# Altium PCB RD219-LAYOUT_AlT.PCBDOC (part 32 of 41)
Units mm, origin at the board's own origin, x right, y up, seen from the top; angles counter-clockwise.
Board outline 209.75 x 159.97 mm, 2 copper layers (TOP, BOTTOM), stack 0 mm thick; 398 components, 199 nets, 1469 pads, 0 vias.
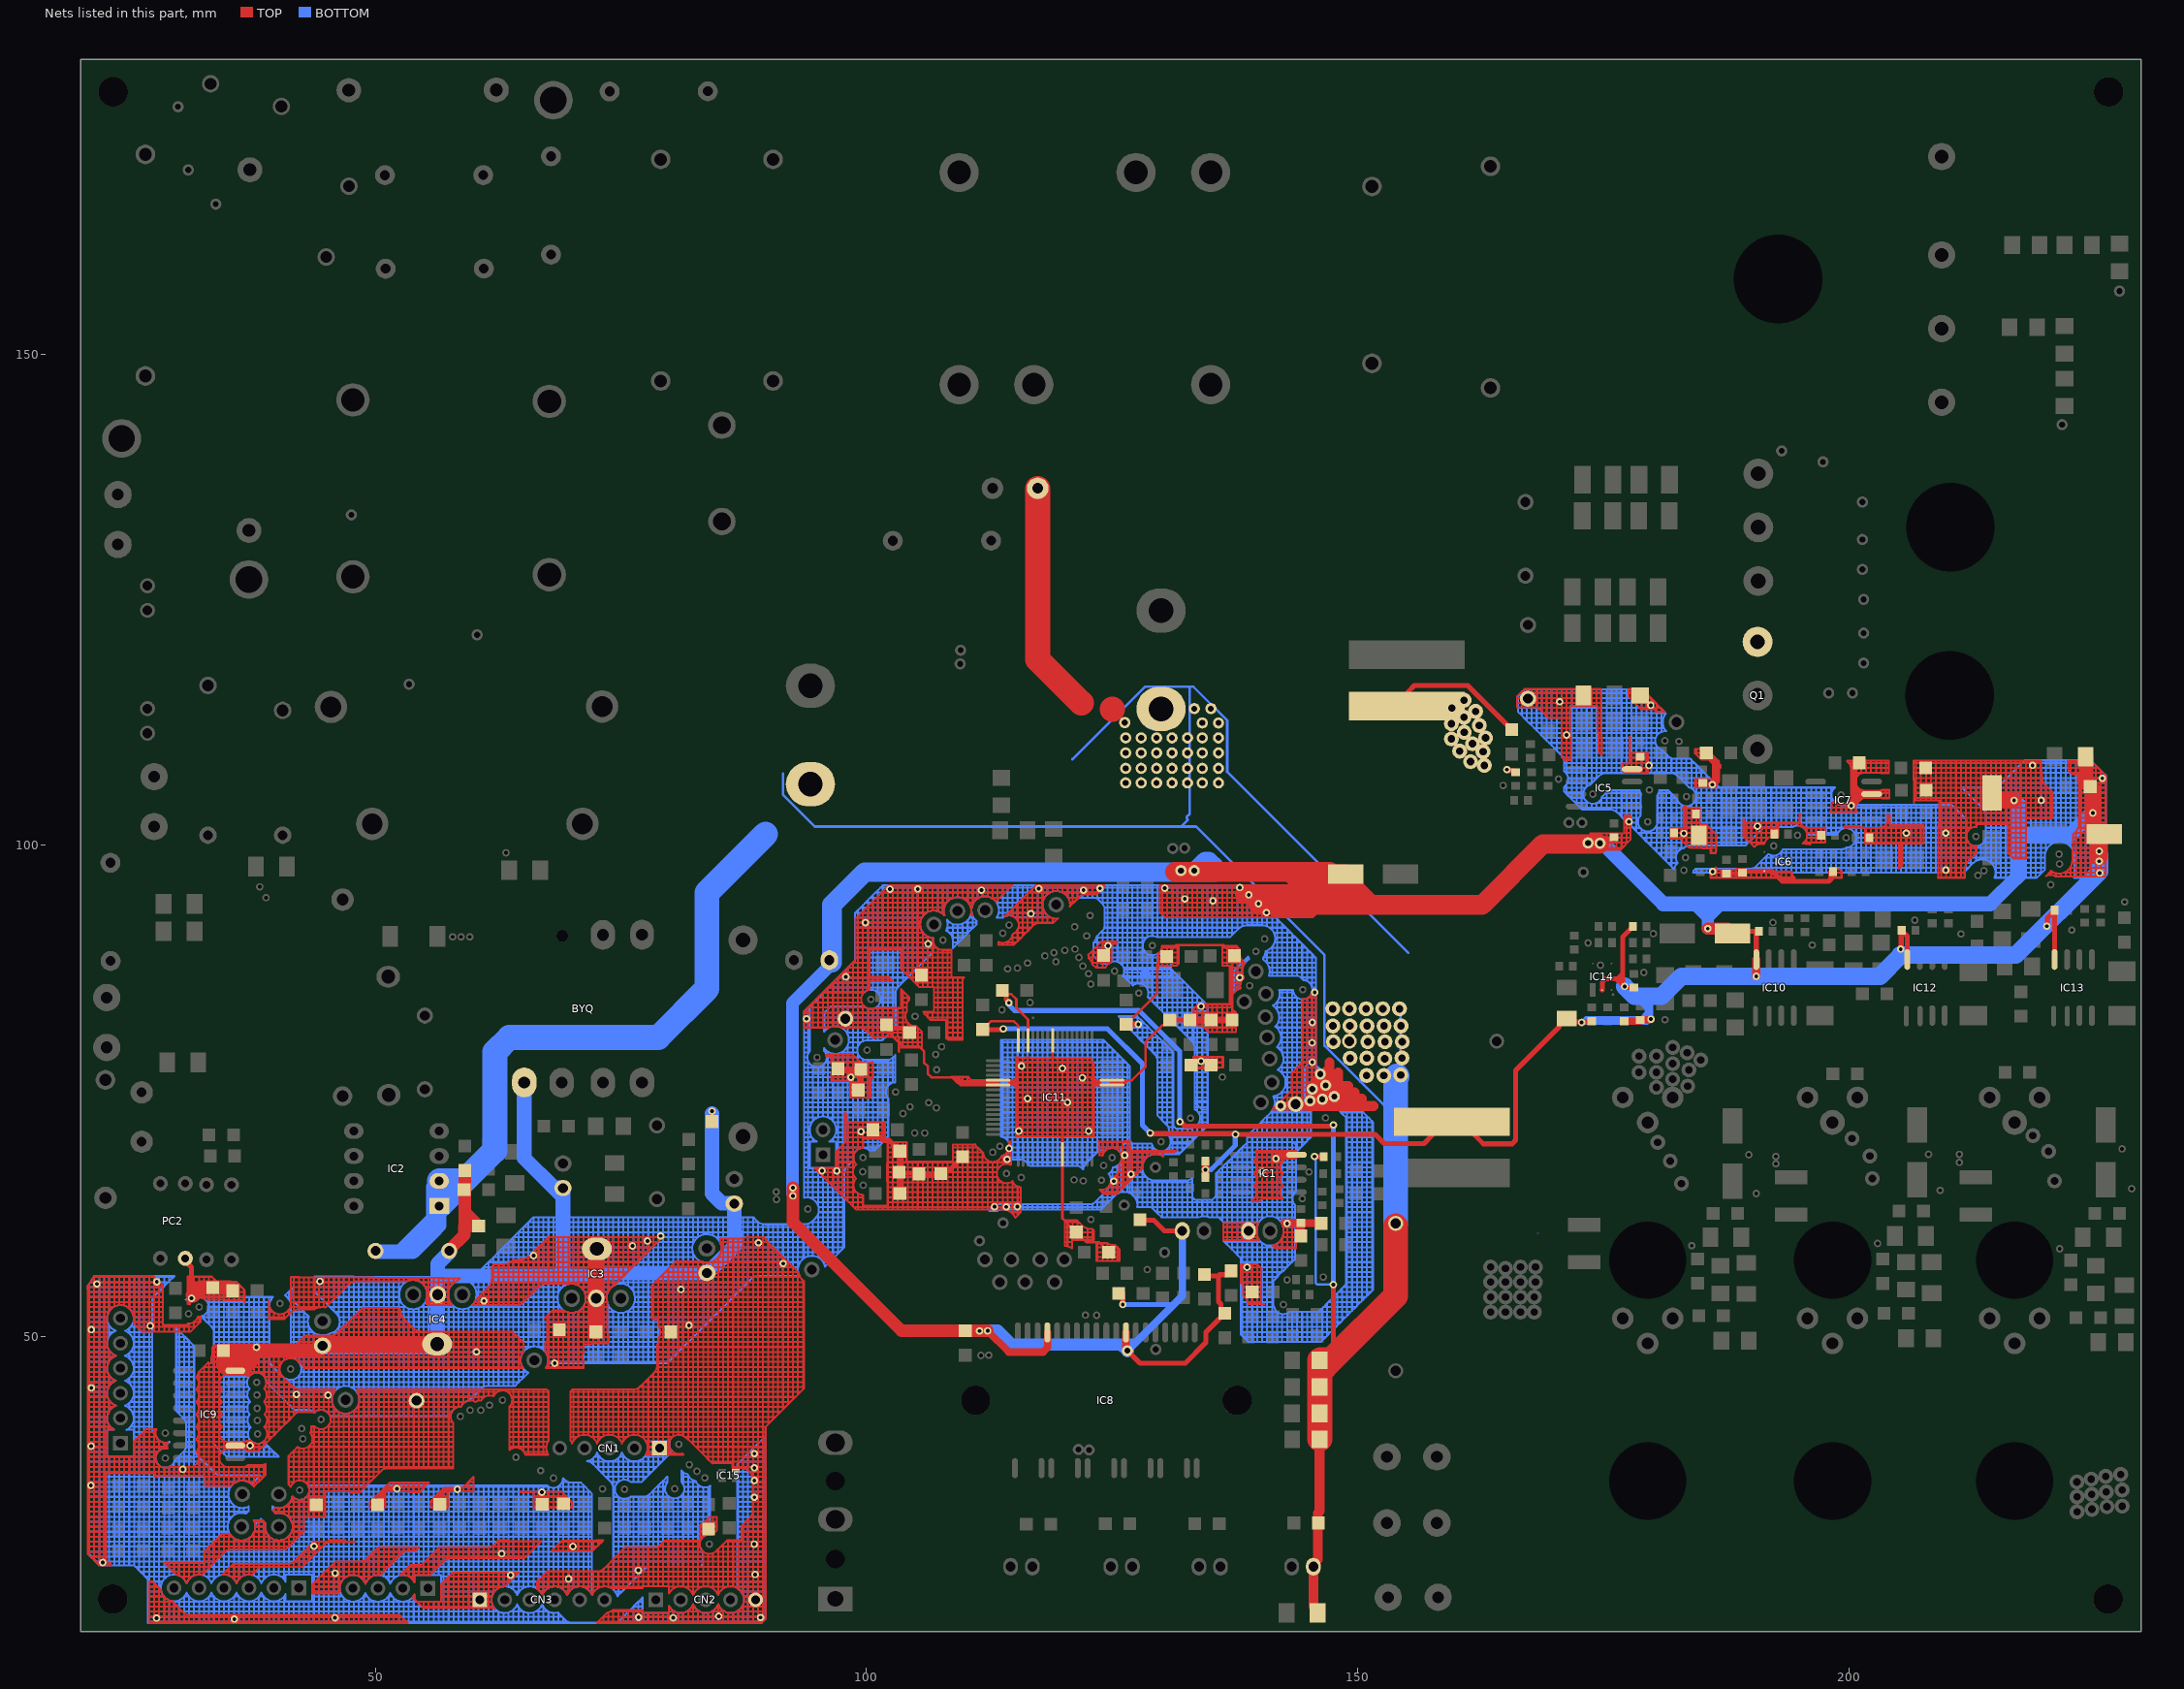
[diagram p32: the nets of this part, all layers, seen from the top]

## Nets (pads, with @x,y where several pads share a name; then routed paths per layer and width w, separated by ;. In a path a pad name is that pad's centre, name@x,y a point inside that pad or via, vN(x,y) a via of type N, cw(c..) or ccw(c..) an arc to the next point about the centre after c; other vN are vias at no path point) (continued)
GND: (continued)
  BOTTOM w0.203: 124.205,91.63 ccw(c123.505,91.831) 124.234,91.831 ; 124.205,91.63 ccw(c123.505,91.831) 124.234,91.831 ; 124.222,93.66 cw(c123.505,93.533) 124.234,93.533 ; 124.222,93.66 cw(c123.505,93.533) 124.234,93.533 ; 124.222,93.66 124.521,93.66 ; 124.234,91.831 124.234,92.136 ; 124.234,92.136 124.521,92.136 ; 124.234,92.136 124.234,92.644 ; 124.234,92.644 124.234,93.152 ; 124.234,92.644 124.521,92.644 ; 124.234,93.152 124.521,93.152 ; 124.234,93.152 124.234,93.533 ; 124.281,64.704 124.521,64.704 ; 124.281,64.704 124.421,64.843 ; 124.394,79.944 124.521,79.817 ; 124.421,64.843 ccw(c123.906,65.359) 124.521,64.968 ; 124.421,64.843 ccw(c123.906,65.359) 124.521,64.968 ; 124.521,63.599 124.521,63.688 ; 124.521,63.599 124.61,63.688 ; 124.521,63.688 124.61,63.688 ; 124.521,63.688 124.521,64.196 ; 124.521,64.196 125.029,64.196 ; 124.521,64.196 124.521,64.704 ; 124.521,64.704 125.029,64.704 ; 124.521,64.704 124.521,64.968 ; 124.521,64.968 ccw(c123.906,65.359) 124.619,65.212 ; 124.521,64.968 ccw(c123.906,65.359) 124.619,65.212 ; 124.521,69.09 124.521,69.276 ; 124.521,69.276 124.521,69.784 ; 124.521,69.276 125.029,69.276 ; 124.521,69.784 124.521,70.292 ; 124.521,69.784 125.029,69.784 ; 124.521,70.292 124.521,70.8 ; 124.521,70.292 125.029,70.292 ; 124.521,70.8 124.521,71.308 ; 124.521,70.8 125.029,70.8 ; 124.521,71.308 124.521,71.816 ; 124.521,71.308 125.029,71.308 ; 124.521,71.816 124.521,72.324 ; 124.521,71.816 125.029,71.816 ; 124.521,72.324 124.521,72.832 ; 124.521,72.324 125.029,72.324 ; 124.521,72.832 124.521,73.34 ; 124.521,72.832 125.029,72.832 ; 124.521,73.34 124.521,73.848 ; 124.521,73.34 125.029,73.34 ; 124.521,73.848 124.521,74.356 ; 124.521,73.848 125.029,73.848 ; 124.521,74.356 124.521,74.864 ; 124.521,74.356 125.029,74.356 ; 124.521,74.864 124.521,75.372 ; 124.521,74.864 125.029,74.864 ; 124.521,75.372 124.521,75.88 ; 124.521,75.372 125.029,75.372 ; 124.521,75.88 124.521,76.388 ; 124.521,75.88 125.029,75.88 ; 124.521,76.388 124.521,76.896 ; 124.521,76.388 125.029,76.388 ; 124.521,76.896 124.521,77.404 ; 124.521,76.896 125.029,76.896 ; 124.521,77.404 124.521,77.912 ; 124.521,77.404 125.029,77.404 ; 124.521,77.912 124.521,78.42 ; 124.521,77.912 125.029,77.912 ; 124.521,78.42 124.521,78.928 ; 124.521,78.42 125.029,78.42 ; 124.521,78.928 124.521,79.436 ; 124.521,78.928 125.029,78.928 ; 124.521,79.436 124.521,79.817 ; 124.521,79.436 124.902,79.436 ; 124.521,79.817 124.902,79.436 ; 124.521,87.934 124.521,88.072 ; 124.521,88.072 124.521,88.58 ; 124.521,88.072 124.786,88.072 ; 124.521,88.58 124.521,89.088 ; 124.521,88.58 125.029,88.58 ; 124.521,89.088 pad.@124.521,89.596 ; 124.521,89.088 125.029,89.088 ; pad.@124.521,89.596 pad.@124.521,90.104 ; pad.@124.521,89.596 125.029,89.596 ; pad.@124.521,90.104 124.521,90.612 ; pad.@124.521,90.104 125.029,90.104 ; 124.521,90.612 124.521,91.12 ; 124.521,90.612 125.029,90.612 ; 124.521,91.12 124.521,91.628 ; 124.521,91.12 125.029,91.12 ; 124.521,91.628 124.521,92.136 ; 124.521,91.628 125.029,91.628 ; 124.521,92.136 124.521,92.644 ; 124.521,92.136 125.029,92.136 ; 124.521,92.644 124.521,93.152 ; 124.521,92.644 125.029,92.644 ; 124.521,93.152 124.521,93.66 ; 124.521,93.152 125.029,93.152 ; 124.521,93.66 125.029,93.66 ; 124.521,93.66 124.521,94.168 ; 124.521,94.168 125.029,94.168 ; 124.521,94.168 124.521,94.676 ; 124.521,94.676 125.029,94.676 ; 124.521,94.676 124.521,95.184 ; 124.521,95.184 125.029,95.184 ; 124.521,95.184 124.521,95.692 ; 124.521,95.692 125.029,95.692 ; 124.521,95.692 124.521,95.946 ; 124.521,95.946 125.029,95.946 ; 124.61,63.688 125.029,64.107 ; 124.619,65.212 ccw(c123.906,65.359) 124.625,65.245 cw(c123.906,65.359) 124.619,65.212 ; 124.619,65.212 125.029,65.212 ; 124.786,88.072 cw(c125.249,87.205) 125.028,88.163 cw(c125.249,87.205) 125.029,88.163 ; 124.833,66.736 ccw(c124.133,67.425) 125.029,67.023 ; 124.833,66.736 125.029,66.736 ; 124.845,66.228 cw(c123.911,65.923) 124.894,65.923 cw(c123.911,65.923) pad.@124.872,65.72 ; 124.845,66.228 125.029,66.228 ; pad.@124.872,65.72 pad.@125.029,65.72 ; 124.902,79.436 125.029,79.309 ; 125.029,64.107 125.029,64.196 ; 125.029,64.107 125.118,64.196 ; 125.029,64.196 125.029,64.704 ; 125.029,64.196 125.118,64.196 ; 125.029,64.704 125.029,65.212 ; 125.029,64.704 125.537,64.704 ; 125.029,65.212 pad.@125.029,65.72 ; 125.029,65.212 125.537,65.212 ; pad.@125.029,65.72 125.029,66.228 ; pad.@125.029,65.72 125.537,65.72 ; 125.029,66.228 125.029,66.736 ; 125.029,66.228 125.537,66.228 ; 125.029,66.736 125.537,66.736 ; 125.029,66.736 125.029,67.023 ; 125.029,67.023 ccw(c124.133,67.425) 125.03,67.025 ccw(c124.133,67.425) 125.098,67.244 ; 125.029,69.276 125.029,69.784 ; 125.029,69.276 125.537,69.276 ; 125.029,69.276 125.029,69.21 cw(c124.994,68.228) 125.537,69.047 ; 125.029,69.784 125.029,70.292 ; 125.029,69.784 125.537,69.784 ; 125.029,70.292 125.029,70.8 ; 125.029,70.292 125.537,70.292 ; 125.029,70.8 125.029,71.308 ; 125.029,70.8 125.537,70.8 ; 125.029,71.308 125.029,71.816 ; 125.029,71.308 125.537,71.308 ; 125.029,71.816 125.029,72.324 ; 125.029,71.816 125.537,71.816 ; 125.029,72.324 125.029,72.832 ; 125.029,72.324 125.537,72.324 ; 125.029,72.832 125.029,73.34 ; 125.029,72.832 125.537,72.832 ; 125.029,73.34 125.029,73.848 ; 125.029,73.34 125.537,73.34 ; 125.029,73.848 125.029,74.356 ; 125.029,73.848 125.537,73.848 ; 125.029,74.356 125.029,74.864 ; 125.029,74.356 125.537,74.356 ; 125.029,74.864 125.029,75.372 ; 125.029,74.864 125.537,74.864 ; 125.029,75.372 125.029,75.88 ; 125.029,75.372 125.537,75.372 ; 125.029,75.88 125.029,76.388 ; 125.029,75.88 125.537,75.88 ; 125.029,76.388 125.029,76.896 ; 125.029,76.388 125.537,76.388 ; 125.029,76.896 125.029,77.404 ; 125.029,76.896 125.537,76.896 ; 125.029,77.404 125.029,77.912 ; 125.029,77.404 125.537,77.404 ; 125.029,77.912 125.029,78.42 ; 125.029,77.912 125.537,77.912 ; 125.029,78.42 125.029,78.928 ; 125.029,78.42 125.537,78.42 ; 125.029,78.928 125.029,79.309 ; 125.029,78.928 125.41,78.928 ; 125.029,79.309 125.41,78.928 ; 125.029,88.163 cw(c125.249,87.205) 125.537,88.145 ; 125.029,88.163 125.029,88.58 ; 125.029,88.58 125.029,89.088 ; 125.029,88.58 125.537,88.58 ; 125.029,89.088 125.029,89.596 ; 125.029,89.088 125.537,89.088 ; 125.029,89.596 125.537,89.596 ; 125.029,89.596 125.029,90.104 ; 125.029,90.104 125.029,90.612 ; 125.029,90.104 125.537,90.104 ; 125.029,90.612 125.029,91.12 ; 125.029,90.612 125.537,90.612 ; 125.029,91.12 125.029,91.628 ; 125.029,91.12 125.537,91.12 ; 125.029,91.628 125.029,92.136 ; 125.029,91.628 125.537,91.628 ; 125.029,92.136 125.029,92.644 ; 125.029,92.136 125.537,92.136 ; 125.029,92.644 125.029,93.152 ; 125.029,92.644 125.537,92.644 ; 125.029,93.152 125.029,93.66 ; 125.029,93.152 125.537,93.152 ; 125.029,93.66 125.029,94.168 ; 125.029,93.66 125.537,93.66 ; 125.029,94.168 125.029,94.676 ; 125.029,94.168 125.537,94.168 ; 125.029,94.676 125.029,95.184 ; 125.029,94.676 125.537,94.676 ; 125.029,95.184 125.029,95.692 ; 125.029,95.184 125.537,95.184 ; 125.029,95.692 125.029,95.946 ; 125.029,95.692 125.537,95.692 ; 125.029,95.946 125.537,95.946 ; 125.098,67.244 ccw(c124.133,67.425) 125.1,67.252 ; 125.098,67.244 125.537,67.244 ; 125.118,64.196 125.267,64.345 cw(c126.222,63.389) 125.537,64.554 ; 125.41,78.928 125.537,78.801 ; 125.537,64.554 cw(c126.222,63.389) 125.547,64.56 cw(c126.222,63.389) 125.91,64.704 ; 125.537,64.554 125.537,64.704 ; 125.537,64.704 125.537,65.212 ; 125.537,64.704 125.91,64.704 ; 125.537,65.212 125.537,65.72 ; 125.537,65.212 125.918,65.212 ; 125.537,65.72 125.918,65.72 ; 125.537,65.72 125.537,66.228 ; 125.537,66.228 125.537,66.736 ; 125.537,66.228 125.918,66.228 ; 125.537,66.736 125.537,67.244 ; 125.537,66.736 125.918,66.736 ; 125.537,67.244 125.918,67.244 ; 125.537,69.047 cw(c124.994,68.228) 125.543,69.043 cw(c124.994,68.228) 125.815,68.768 ; 125.537,69.047 125.537,69.276 ; 125.537,69.276 125.918,69.276 ; 125.537,69.276 125.537,69.784 ; 125.537,69.784 125.537,70.292 ; 125.537,69.784 126.045,69.784 ; 125.537,70.292 126.045,70.292 ; 125.537,70.292 125.537,70.8 ; 125.537,70.8 125.537,71.308 ; 125.537,70.8 126.045,70.8 ; 125.537,71.308 125.537,71.816 ; 125.537,71.308 126.045,71.308 ; 125.537,71.816 125.537,72.324 ; 125.537,71.816 126.045,71.816 ; 125.537,72.324 125.537,72.832 ; 125.537,72.324 126.045,72.324 ; 125.537,72.832 125.537,73.34 ; 125.537,72.832 126.045,72.832 ; 125.537,73.34 125.537,73.848 ; 125.537,73.34 126.045,73.34 ; 125.537,73.848 125.537,74.356 ; 125.537,73.848 126.045,73.848 ; 125.537,74.356 125.537,74.864 ; 125.537,74.356 126.045,74.356 ; 125.537,74.864 125.537,75.372 ; 125.537,74.864 126.045,74.864 ; 125.537,75.372 125.537,75.88 ; 125.537,75.372 126.045,75.372 ; 125.537,75.88 125.537,76.388 ; 125.537,75.88 126.045,75.88 ; 125.537,76.388 125.537,76.896 ; 125.537,76.388 126.045,76.388 ; 125.537,76.896 125.537,77.404 ; 125.537,76.896 126.045,76.896 ; 125.537,77.404 126.045,77.404 ; 125.537,77.404 125.537,77.912 ; 125.537,77.912 126.045,77.912 ; 125.537,77.912 125.537,78.42 ; 125.537,78.42 125.537,78.801 ; 125.537,78.42 125.918,78.42 ; 125.537,78.801 125.918,78.42 ; 125.537,88.145 cw(c125.249,87.205) 125.71,88.073 cw(c125.249,87.205) 125.711,88.072 ; 125.537,88.145 125.537,88.58 ; 125.537,88.58 125.537,89.088 ; 125.537,88.58 126.045,88.58 ; 125.537,89.088 125.537,89.596 ; 125.537,89.088 126.045,89.088 ; 125.537,89.596 125.537,90.104 ; 125.537,89.596 126.045,89.596 ; 125.537,90.104 125.537,90.612 ; 125.537,90.104 126.045,90.104 ; 125.537,90.612 125.537,91.12 ; 125.537,90.612 126.045,90.612 ; 125.537,91.12 125.537,91.628 ; 125.537,91.12 126.045,91.12 ; 125.537,91.628 125.537,92.136 ; 125.537,91.628 126.045,91.628 ; 125.537,92.136 125.537,92.644 ; 125.537,92.136 126.045,92.136 ; 125.537,92.644 125.537,93.152 ; 125.537,92.644 126.045,92.644 ; 125.537,93.152 125.537,93.66 ; 125.537,93.152 126.045,93.152 ; 125.537,93.66 125.537,94.168 ; 125.537,93.66 126.045,93.66 ; 125.537,94.168 125.537,94.676 ; 125.537,94.168 126.045,94.168 ; 125.537,94.676 125.537,95.184 ; 125.537,94.676 126.045,94.676 ; 125.537,95.184 125.537,95.692 ; 125.537,95.184 126.045,95.184 ; 125.537,95.692 125.537,95.946 ; 125.537,95.692 126.045,95.692 ; 125.537,95.946 126.045,95.946 ; 125.711,88.072 126.045,88.072 ; 125.756,82.484 125.664,82.611 126.045,82.611 ; 125.756,82.484 126.045,82.087 ; 125.756,82.484 126.045,82.484 ; 125.815,68.768 cw(c124.994,68.228) pad.@125.918,68.562 ; 125.815,68.768 125.918,68.768 ; 125.853,67.752 ccw(c124.994,68.228) 125.918,67.895 ; 125.853,67.752 125.918,67.752 ; 125.91,64.704 cw(c126.222,63.389) 125.918,64.706 ; 125.918,64.706 cw(c126.222,63.389) 126.045,64.729 ; 125.918,64.706 cw(c126.222,63.389) 126.045,64.729 ; 125.918,64.706 125.918,65.212 ; 125.918,65.212 126.045,65.212 ; 125.918,65.212 125.918,65.72 ; 125.918,65.72 126.045,65.72 ; 125.918,65.72 125.918,66.228 ; 125.918,66.228 126.045,66.228 ; 125.918,66.228 125.918,66.736 ; 125.918,66.736 126.045,66.736 ; 125.918,66.736 125.918,67.244 ; 125.918,67.244 125.918,67.752 ; 125.918,67.244 126.045,67.244 ; 125.918,67.752 126.045,67.752 ; 125.918,67.752 125.918,67.895 ; 125.918,67.895 ccw(c124.994,68.228) pad.@125.976,68.26 ; 125.918,67.895 ccw(c124.994,68.228) 125.976,68.228 ccw(c124.994,68.228) pad.@125.976,68.26 ; pad.@125.918,68.562 cw(c124.994,68.228) pad.@125.976,68.26 ; pad.@125.918,68.562 cw(c124.994,68.228) pad.@125.976,68.26 ; pad.@125.918,68.562 125.918,68.768 ; 125.918,68.768 125.918,69.276 ; 125.918,68.768 pad.@126.045,68.768 ; 125.918,69.276 126.045,69.403 ; 125.918,69.276 126.045,69.276 ; 125.918,78.42 126.045,78.293 ; pad.@125.976,68.26 pad.@126.045,68.26 ; 126.045,64.729 cw(c126.222,63.389) 126.535,64.704 ; 126.045,64.729 cw(c126.222,63.389) 126.535,64.704 ; 126.045,64.729 126.045,65.212 ; 126.045,65.212 126.553,65.212 ; 126.045,65.212 126.045,65.72 ; 126.045,65.72 126.045,66.228 ; 126.045,65.72 126.553,65.72 ; 126.045,66.228 126.045,66.736 ; 126.045,66.228 126.553,66.228 ; 126.045,66.736 126.045,67.244 ; 126.045,66.736 126.553,66.736 ; 126.045,67.244 126.045,67.752 ; 126.045,67.244 126.553,67.244 ; 126.045,67.752 pad.@126.045,68.26 ; 126.045,67.752 126.553,67.752 ; pad.@126.045,68.26 pad.@126.045,68.768 ; pad.@126.045,68.26 pad.@126.553,68.26 ; pad.@126.045,68.768 126.045,69.276 ; pad.@126.045,68.768 126.553,68.768 ; 126.045,69.276 126.553,69.276 ; 126.045,69.276 126.045,69.403 ; 126.045,69.403 126.045,69.784 ; 126.045,69.403 126.299,69.657 126.553,69.657 ; 126.045,69.784 126.045,70.292 ; 126.045,69.784 126.553,69.784 ; 126.045,70.292 126.553,70.292 ; 126.045,70.292 126.045,70.8 ; 126.045,70.8 126.045,71.308 ; 126.045,70.8 126.553,70.8 ; 126.045,71.308 126.045,71.816 ; 126.045,71.308 126.553,71.308 ; 126.045,71.816 126.045,72.324 ; 126.045,71.816 126.553,71.816 ; 126.045,72.324 126.045,72.832 ; 126.045,72.324 126.553,72.324 ; 126.045,72.832 126.045,73.34 ; 126.045,72.832 126.553,72.832 ; 126.045,73.34 126.045,73.848 ; 126.045,73.34 126.553,73.34 ; 126.045,73.848 126.045,74.356 ; 126.045,73.848 126.553,73.848 ; 126.045,74.356 126.045,74.864 ; 126.045,74.356 126.553,74.356 ; 126.045,74.864 126.045,75.372 ; 126.045,74.864 126.553,74.864 ; 126.045,75.372 126.045,75.88 ; 126.045,75.372 126.553,75.372 ; 126.045,75.88 126.045,76.388 ; 126.045,75.88 126.553,75.88 ; 126.045,76.388 126.045,76.896 ; 126.045,76.388 126.553,76.388 ; 126.045,76.896 126.045,77.404 ; 126.045,76.896 126.553,76.896 ; 126.045,77.404 126.553,77.404 ; 126.045,77.404 126.045,77.912 ; 126.045,77.912 126.426,77.912 ; 126.045,77.912 126.045,78.293 ; 126.045,78.293 126.426,77.912 ; 126.045,82.087 126.126,81.976 ; 126.045,82.087 126.045,82.484 ; 126.045,82.484 126.553,82.484 ; 126.045,82.484 126.045,82.611 ; 126.045,82.611 126.553,82.611 ; 126.045,88.072 126.045,88.58 ; 126.045,88.072 126.553,88.072 ; 126.045,88.58 126.045,89.088 ; 126.045,88.58 126.553,88.58 ; 126.045,89.088 126.045,89.596 ; 126.045,89.088 126.553,89.088 ; 126.045,89.596 126.045,90.104 ; 126.045,89.596 126.553,89.596 ; 126.045,90.104 126.045,90.612 ; 126.045,90.104 126.553,90.104 ; 126.045,90.612 126.045,91.12 ; 126.045,90.612 126.553,90.612 ; 126.045,91.12 126.045,91.628 ; 126.045,91.12 126.553,91.12 ; 126.045,91.628 126.045,92.136 ; 126.045,91.628 126.553,91.628 ; 126.045,92.136 126.045,92.644 ; 126.045,92.136 126.553,92.136 ; 126.045,92.644 126.045,93.152 ; 126.045,92.644 126.553,92.644 ; 126.045,93.152 126.045,93.66 ; 126.045,93.152 126.553,93.152 ; 126.045,93.66 126.045,94.168 ; 126.045,93.66 126.553,93.66 ; 126.045,94.168 126.045,94.676 ; 126.045,94.168 126.553,94.168 ; 126.045,94.676 126.045,95.184 ; 126.045,94.676 126.553,94.676 ; 126.045,95.184 126.045,95.692 ; 126.045,95.184 126.553,95.184 ; 126.045,95.692 126.045,95.946 ; 126.045,95.692 126.553,95.692 ; 126.045,95.946 126.553,95.946 ; 126.076,86.675 ccw(c125.249,87.205) 126.112,86.735 ; 126.076,86.675 126.172,86.675 ; 126.112,86.735 ccw(c125.249,87.205) 126.22,87.056 ; 126.112,86.735 ccw(c125.249,87.205) 126.22,87.056 ; 126.112,86.735 126.172,86.675 ; 126.126,81.976 126.163,81.925 126.553,81.535 ; 126.126,81.976 126.553,81.976 ; 126.163,87.564 cw(c125.249,87.205) 126.217,87.374 ; 126.163,87.564 126.553,87.564 ; 126.172,86.675 126.299,86.548 ; 126.172,86.675 126.553,86.675 ; 126.217,87.374 cw(c125.249,87.205) 126.231,87.205 cw(c125.249,87.205) 126.22,87.056 ; 126.217,87.374 cw(c125.249,87.205) 126.22,87.056 ; 126.217,87.374 126.553,87.374 ; 126.22,87.056 126.553,87.056 ; 126.299,86.548 126.553,86.548 ; 126.299,86.548 126.553,86.294 ; 126.426,77.912 126.553,77.785 ; 126.535,64.704 cw(c126.222,63.389) 126.553,64.7 ; 126.535,64.704 cw(c126.222,63.389) 126.553,64.7 ; 126.535,64.704 126.553,64.704 ; 126.553,64.7 cw(c126.222,63.389) 126.74,64.637 ; 126.553,64.7 cw(c126.222,63.389) 126.74,64.637 ; 126.553,64.7 126.553,64.704 ; 126.553,64.704 126.807,64.704 ; 126.553,64.704 126.553,65.212 ; 126.553,65.212 126.807,65.212 ; 126.553,65.212 126.553,65.72 ; 126.553,65.72 126.553,66.228 ; 126.553,65.72 126.807,65.72 ; 126.553,66.228 pad.@126.807,66.228 ; 126.553,66.228 126.553,66.736 ; 126.553,66.736 pad.@126.807,66.736 ; 126.553,66.736 126.553,67.244 ; 126.553,67.244 126.553,67.752 ; 126.553,67.244 126.807,67.244 ; 126.553,67.752 pad.@126.553,68.26 ; 126.553,67.752 126.807,67.752 ; pad.@126.553,68.26 126.807,68.26 ; pad.@126.553,68.26 126.553,68.768 ; 126.553,68.768 126.553,69.276 ; 126.553,68.768 126.807,68.768 ; 126.553,69.276 126.553,69.657 ; 126.553,69.276 126.807,69.276 ; 126.553,69.657 126.807,69.657 ; 126.553,69.657 126.553,69.784 ; 126.553,69.784 126.553,70.292 ; 126.553,69.784 126.807,69.784 ; 126.553,70.292 126.553,70.8 ; 126.553,70.292 126.807,70.292 ; 126.553,70.8 126.553,71.308 ; 126.553,70.8 126.807,70.8 ; 126.553,71.308 126.553,71.816 ; 126.553,71.308 126.807,71.308 ; 126.553,71.816 126.553,72.324 ; 126.553,71.816 126.807,71.816 ; 126.553,72.324 126.553,72.832 ; 126.553,72.324 126.807,72.324 ; 126.553,72.832 126.553,73.34 ; 126.553,72.832 126.807,72.832 ; 126.553,73.34 126.553,73.848 ; 126.553,73.34 126.807,73.34 ; 126.553,73.848 126.553,74.356 ; 126.553,73.848 126.807,73.848 ; 126.553,74.356 126.553,74.864 ; 126.553,74.356 126.807,74.356 ; 126.553,74.864 126.553,75.372 ; 126.553,74.864 126.807,74.864 ; 126.553,75.372 126.553,75.88 ; 126.553,75.372 126.807,75.372 ; 126.553,75.88 126.553,76.388 ; 126.553,75.88 126.807,75.88 ; 126.553,76.388 126.553,76.896 ; 126.553,76.388 126.807,76.388 ; 126.553,76.896 126.553,77.404 ; 126.553,76.896 126.807,76.896 ; 126.553,77.404 126.553,77.785 ; 126.553,77.404 126.807,77.404 ; 126.553,77.785 126.807,77.531 126.807,77.404 ; 126.553,81.535 126.553,81.976 ; 126.553,81.535 126.62,81.468 ; 126.553,81.976 126.553,82.484 ; 126.553,81.976 127.061,81.976 ; 126.553,82.484 126.553,82.611 ; 126.553,82.484 127.061,82.484 ; 126.553,82.611 127.061,82.611 ; 126.553,86.294 126.553,86.548 ; 126.553,86.294 126.807,86.04 ; 126.553,86.548 126.553,86.675 ; 126.553,86.548 127.061,86.548 ; 126.553,86.675 126.553,87.056 ; 126.553,86.675 127.061,86.675 ; 126.553,87.056 127.061,87.056 ; 126.553,87.056 126.553,87.374 ; 126.553,87.374 126.553,87.564 ; 126.553,87.374 127.061,87.374 ; 126.553,87.564 126.553,88.072 ; 126.553,87.564 127.061,87.564 ; 126.553,88.072 126.553,88.58 ; 126.553,88.072 127.061,88.072 ; 126.553,88.58 126.553,89.088 ; 126.553,88.58 127.061,88.58 ; 126.553,89.088 126.553,89.596 ; 126.553,89.088 127.061,89.088 ; 126.553,89.596 126.553,90.104 ; 126.553,89.596 127.061,89.596 ; 126.553,90.104 126.553,90.612 ; 126.553,90.104 127.061,90.104 ; 126.553,90.612 126.553,91.12 ; 126.553,90.612 127.061,90.612 ; 126.553,91.12 126.553,91.628 ; 126.553,91.12 127.061,91.12 ; 126.553,91.628 126.553,92.136 ; 126.553,91.628 127.061,91.628 ; 126.553,92.136 126.553,92.644 ; 126.553,92.136 127.061,92.136 ; 126.553,92.644 126.553,93.152 ; 126.553,92.644 127.061,92.644 ; 126.553,93.152 126.553,93.66 ; 126.553,93.152 127.061,93.152 ; 126.553,93.66 126.553,94.168 ; 126.553,93.66 127.061,93.66 ; 126.553,94.168 126.553,94.676 ; 126.553,94.168 127.061,94.168 ; 126.553,94.676 126.553,95.184 ; 126.553,94.676 127.061,94.676 ; 126.553,95.184 126.553,95.692 ; 126.553,95.184 127.061,95.184 ; 126.553,95.692 126.553,95.946 ; 126.553,95.692 127.061,95.692 ; 126.553,95.946 127.061,95.946 ; 126.62,81.468 127.061,81.468 ; 126.62,81.468 127.061,81.027 ; 126.74,64.637 cw(c126.222,63.389) 127.055,64.454 cw(c126.222,63.389) 127.061,64.449 ; 126.74,64.637 126.807,64.704 ; 126.807,64.704 127.061,64.704 ; 126.807,64.704 126.807,65.212 ; 126.807,65.212 126.807,65.72 ; 126.807,65.212 127.061,65.212 ; 126.807,65.72 pad.@126.807,66.228 ; 126.807,65.72 127.061,65.72 ; pad.@126.807,66.228 pad.@127.061,66.228 ; pad.@126.807,66.228 pad.@126.807,66.736 ; pad.@126.807,66.736 126.807,67.244 ; pad.@126.807,66.736 pad.@127.061,66.736 ; 126.807,67.244 126.807,67.752 ; 126.807,67.244 127.061,67.244 ; 126.807,67.752 126.807,68.26 ; 126.807,67.752 127.061,67.752 ; 126.807,68.26 126.807,68.768 ; 126.807,68.26 127.061,68.26 ; 126.807,68.768 126.807,69.276 ; 126.807,68.768 127.061,68.768 ; 126.807,69.276 126.807,69.657 ; 126.807,69.276 127.061,69.276 ; 126.807,69.657 126.807,69.784 ; 126.807,69.657 127.038,69.657 127.061,69.657 ; 126.807,69.784 126.807,70.292 ; 126.807,70.292 126.807,70.8 ; 126.807,70.8 126.807,71.308 ; 126.807,71.308 126.807,71.816 ; 126.807,71.816 126.807,72.324 ; 126.807,72.324 126.807,72.832 ; 126.807,72.832 126.807,73.34 ; 126.807,73.34 126.807,73.848 ; 126.807,73.848 126.807,74.356 ; 126.807,74.356 126.807,74.864 ; 126.807,74.864 126.807,75.372 ; 126.807,75.372 126.807,75.88 ; 126.807,75.88 126.807,76.388 ; 126.807,76.388 126.807,76.896 ; 126.807,76.896 126.807,77.404 ; 126.807,86.04 127.061,86.04 ; 127.061,64.449 cw(c126.222,63.389) 127.307,64.196 ; 127.061,64.449 127.061,64.704 ; 127.061,64.704 127.061,65.212 ; 127.061,64.704 127.569,64.704 ; 127.061,65.212 127.061,65.72 ; 127.061,65.212 127.569,65.212 ; 127.061,65.72 pad.@127.061,66.228 ; 127.061,65.72 127.569,65.72 ; pad.@127.061,66.228 127.569,66.228 ; pad.@127.061,66.228 pad.@127.061,66.736 ; pad.@127.061,66.736 127.061,67.244 ; pad.@127.061,66.736 127.569,66.736 ; 127.061,67.244 127.061,67.752 ; 127.061,67.244 127.569,67.244 ; 127.061,67.752 127.061,68.26 ; 127.061,67.752 127.569,67.752 ; 127.061,68.26 127.061,68.768 ; 127.061,68.26 127.569,68.26 ; 127.061,68.768 127.061,69.276 ; 127.061,68.768 127.569,68.768 ; 127.061,69.276 127.061,69.657 ; 127.061,69.276 127.569,69.276 ; 127.061,69.657 127.569,69.657 ; 127.061,81.027 127.061,81.468 ; 127.061,81.027 127.128,80.96 ; 127.061,81.468 pad.@127.569,81.468 ; 127.061,81.468 127.061,81.976 ; 127.061,81.976 pad.@127.569,81.976 ; 127.061,81.976 127.061,82.484 ; 127.061,82.484 127.569,82.484 ; 127.061,82.484 127.061,82.611 ; 127.061,82.611 127.569,82.611 ; 127.061,86.04 127.569,86.04 ; 127.061,86.04 127.061,86.548 ; 127.061,86.548 127.061,86.675 ; 127.061,86.548 127.569,86.548 ; 127.061,86.675 127.061,87.056 ; 127.061,86.675 127.569,86.675 ; 127.061,87.056 127.061,87.374 ; 127.061,87.056 127.569,87.056 ; 127.061,87.374 127.061,87.564 ; 127.061,87.374 127.569,87.374 ; 127.061,87.564 127.061,88.072 ; 127.061,87.564 127.569,87.564 ; 127.061,88.072 127.061,88.58 ; 127.061,88.072 127.569,88.072 ; 127.061,88.58 127.061,89.088 ; 127.061,88.58 127.569,88.58 ; 127.061,89.088 127.061,89.596 ; 127.061,89.088 127.569,89.088 ; 127.061,89.596 127.061,90.104 ; 127.061,89.596 127.569,89.596 ; 127.061,90.104 127.061,90.612 ; 127.061,90.104 127.569,90.104 ; 127.061,90.612 127.061,91.12 ; 127.061,90.612 127.569,90.612 ; 127.061,91.12 127.061,91.628 ; 127.061,91.12 127.569,91.12 ; 127.061,91.628 127.061,92.136 ; 127.061,91.628 127.569,91.628 ; 127.061,92.136 127.061,92.644 ; 127.061,92.136 127.569,92.136 ; 127.061,92.644 127.061,93.152 ; 127.061,92.644 127.569,92.644 ; 127.061,93.152 127.061,93.66 ; 127.061,93.152 127.569,93.152 ; 127.061,93.66 127.061,94.168 ; 127.061,93.66 127.569,93.66 ; 127.061,94.168 127.061,94.676 ; 127.061,94.168 127.569,94.168 ; 127.061,94.676 127.061,95.184 ; 127.061,94.676 127.569,94.676 ; 127.061,95.184 127.061,95.692 ; 127.061,95.184 127.569,95.184 ; 127.061,95.692 127.061,95.946 ; 127.061,95.692 127.569,95.692 ; 127.061,95.946 127.569,95.946 ; 127.128,80.96 127.569,80.96 ; 127.128,80.96 127.569,80.519 ; 127.307,64.196 cw(c126.222,63.389) 127.541,63.688 ; 127.307,64.196 127.569,64.196 ; 127.541,63.688 cw(c126.222,63.389) 127.569,63.507 cw(c126.222,63.389) 127.569,63.505 ; 127.541,63.688 127.569,63.688 ; 127.558,63.18 ccw(c126.222,63.389) 127.569,63.273 ; 127.558,63.18 127.569,63.18 ; 127.569,63.18 128.077,63.18 ; 127.569,63.18 127.569,63.273 ; 127.569,63.273 ccw(c126.222,63.389) 127.569,63.505 ; 127.569,63.505 127.569,63.688 ; 127.569,63.688 128.077,63.688 ; 127.569,63.688 127.569,64.196 ; 127.569,64.196 127.569,64.704 ; 127.569,64.196 128.077,64.196 ; 127.569,64.704 127.569,65.212 ; 127.569,64.704 128.077,64.704 ; 127.569,65.212 127.569,65.72 ; 127.569,65.212 128.077,65.212 ; 127.569,65.72 127.569,66.228 ; 127.569,65.72 128.077,65.72 ; 127.569,66.228 127.569,66.736 ; 127.569,66.228 128.077,66.228 ; 127.569,66.736 127.569,67.244 ; 127.569,66.736 128.077,66.736 ; 127.569,67.244 127.569,67.752 ; 127.569,67.752 127.569,68.26 ; 127.569,67.752 128.077,67.752 ; 127.569,68.26 127.569,68.768 ; 127.569,68.26 128.077,68.26 ; 127.569,68.768 127.569,69.276 ; 127.569,68.768 128.077,68.768 ; 127.569,69.276 127.569,69.657 ; 127.569,69.276 128.077,69.276 ; 127.569,69.657 128.077,69.657 ; 127.569,80.519 127.569,80.96 ; 127.569,80.519 127.636,80.452 ; 127.569,80.96 pad.@127.569,81.468 ; 127.569,80.96 128.077,80.96 ; pad.@127.569,81.468 pad.@127.569,81.976 ; pad.@127.569,81.468 128.077,81.468 ; pad.@127.569,81.976 127.569,82.484 ; pad.@127.569,81.976 128.077,81.976 ; 127.569,82.484 127.569,82.611 ; 127.569,82.611 128.077,82.103 ; 127.569,85.946 cw(c127.709,84.974) 127.709,85.956 cw(c127.709,84.974) 128.077,85.885 ; 127.569,85.946 127.569,86.04 ; 127.569,86.04 127.569,86.548 ; 127.569,86.04 128.077,86.04 ; 127.569,86.548 127.569,86.675 ; 127.569,86.548 128.077,86.548 ; 127.569,86.675 127.569,87.056 ; 127.569,86.675 128.077,86.675 ; 127.569,87.056 127.569,87.374 ; 127.569,87.056 128.077,87.056 ; 127.569,87.374 127.569,87.564 ; 127.569,87.374 128.077,87.373 ; 127.569,87.564 127.569,88.072 ; 127.569,87.564 128.077,87.564 ; 127.569,88.072 127.569,88.58 ; 127.569,88.072 128.077,88.072 ; 127.569,88.58 127.569,89.088 ; 127.569,88.58 128.077,88.58 ; 127.569,89.088 127.569,89.596 ; 127.569,89.088 128.077,89.088 ; 127.569,89.596 127.569,90.104 ; 127.569,89.596 128.077,89.596 ; 127.569,90.104 127.569,90.612 ; 127.569,90.104 128.077,90.104 ; 127.569,90.612 127.569,91.12 ; 127.569,90.612 128.077,90.612 ; 127.569,91.12 127.569,91.628 ; 127.569,91.12 128.077,91.12 ; 127.569,91.628 127.569,92.136 ; 127.569,91.628 128.077,91.628 ; 127.569,92.136 127.569,92.644 ; 127.569,92.136 128.077,92.136 ; 127.569,92.644 127.569,93.152 ; 127.569,92.644 128.077,92.644 ; 127.569,93.152 127.569,93.66 ; 127.569,93.152 128.077,93.152 ; 127.569,93.66 127.569,94.168 ; 127.569,93.66 128.077,93.66 ; 127.569,94.168 127.569,94.676 ; 127.569,94.168 128.077,94.168 ; 127.569,94.676 127.569,95.184 ; 127.569,94.676 128.077,94.676 ; 127.569,95.184 127.569,95.692 ; 127.569,95.184 128.077,95.184 ; 127.569,95.692 127.569,95.946 ; 127.569,95.692 128.077,95.692 ; 127.569,95.946 128.077,95.946 ; 127.636,80.452 128.077,80.452 ; 127.636,80.452 128.077,80.011 ; 128.077,63.18 128.077,63.688 ; 128.077,63.18 128.585,63.18 ; 128.077,63.688 128.077,64.196 ; 128.077,63.688 128.585,63.688 ; 128.077,64.196 128.077,64.704 ; 128.077,64.196 128.585,64.196 ; 128.077,64.704 128.077,65.212 ; 128.077,64.704 128.585,64.704 ; 128.077,65.212 128.077,65.72 ; 128.077,65.212 128.585,65.212 ; 128.077,65.72 128.077,66.228 ; 128.077,65.72 128.585,65.72 ; 128.077,66.228 128.077,66.736 ; 128.077,66.228 128.507,66.228 ; 128.077,66.736 128.077,67.009 ; 128.077,66.736 128.153,66.736 ; 128.077,67.009 ccw(c129.41,67.234) 128.079,66.999 ccw(c129.41,67.234) 128.153,66.736 ; 128.077,67.459 cw(c129.41,67.234) 128.079,67.469 cw(c129.41,67.234) 128.161,67.752 ; 128.077,67.459 128.077,67.752 ; 128.077,67.752 128.077,68.26 ; 128.077,67.752 128.161,67.752 ; 128.077,68.26 128.077,68.768 ; 128.077,68.26 128.53,68.26 ; 128.077,68.768 128.585,68.768 ; 128.077,68.768 128.077,69.276 ; 128.077,69.276 128.585,69.276 ; 128.077,69.276 128.077,69.657 ; 128.077,69.657 128.585,69.657 ; 128.077,80.011 128.077,80.452 ; 128.077,80.011 128.144,79.944 ; 128.077,80.452 128.585,80.452 ; 128.077,80.452 128.077,80.96 ; 128.077,80.96 128.585,80.96 ; 128.077,80.96 128.077,81.468 ; 128.077,81.468 128.585,81.468 ; 128.077,81.468 128.077,81.976 ; 128.077,81.976 128.204,81.976 ; 128.077,81.976 128.077,82.103 ; 128.077,82.103 128.204,81.976 ; 128.077,85.885 cw(c127.709,84.974) 128.517,85.532 ; 128.077,85.885 128.077,86.04 ; 128.077,86.04 128.077,86.548 ; 128.077,86.04 128.585,86.04 ; 128.077,86.548 128.077,86.675 ; 128.077,86.548 128.585,86.548 ; 128.077,86.675 128.077,87.056 ; 128.077,86.675 128.585,86.675 ; 128.077,87.056 128.077,87.373 ; 128.077,87.056 128.585,87.056 ; 128.077,87.373 128.077,87.564 ; 128.077,87.373 128.585,87.373 ; 128.077,87.564 128.077,88.072 ; 128.077,87.564 128.585,87.564 ; 128.077,88.072 128.077,88.58 ; 128.077,88.072 128.585,88.072 ; 128.077,88.58 128.077,89.088 ; 128.077,88.58 128.585,88.58 ; 128.077,89.088 128.077,89.596 ; 128.077,89.088 128.413,89.088 ; 128.077,89.596 128.077,90.104 ; 128.077,89.596 128.129,89.596 ; 128.077,90.104 128.077,90.612 ; 128.077,90.104 128.157,90.104 ; 128.077,90.612 128.077,91.12 ; 128.077,90.612 128.539,90.612 ; 128.077,91.12 128.077,91.628 ; 128.077,91.12 128.585,91.12 ; 128.077,91.628 128.077,92.136 ; 128.077,91.628 128.585,91.628 ; 128.077,92.136 128.077,92.644 ; 128.077,92.136 128.585,92.136 ; 128.077,92.644 128.077,93.152 ; 128.077,92.644 128.585,92.644 ; 128.077,93.152 128.585,93.152 ; 128.077,93.152 128.077,93.66 ; 128.077,93.66 128.585,93.66 ; 128.077,93.66 128.077,94.168 ; 128.077,94.168 128.585,94.168 ; 128.077,94.168 128.077,94.676 ; 128.077,94.676 128.585,94.676 ; 128.077,94.676 128.077,95.184 ; 128.077,95.184 128.585,95.184 ; 128.077,95.184 128.077,95.692 ; 128.077,95.692 128.585,95.692 ; 128.077,95.692 128.077,95.946 ; 128.077,95.946 128.585,95.946 ; 128.129,89.596 ccw(c129.091,89.799) 128.13,89.595 ccw(c129.091,89.799) 128.408,89.092 ccw(c129.091,89.799) 128.413,89.088 ; 128.129,89.596 cw(c129.091,89.799) 128.108,89.799 cw(c129.091,89.799) 128.157,90.104 ; 128.144,79.944 128.585,79.944 ; 128.144,79.944 128.585,79.503 ; 128.153,66.736 ccw(c129.41,67.234) 128.157,66.728 ccw(c129.41,67.234) 128.507,66.228 ; 128.157,90.104 cw(c129.091,89.799) 128.539,90.612 ; 128.161,67.752 cw(c129.41,67.234) 128.53,68.26 ; 128.204,81.976 128.585,81.595 ; 128.413,89.088 ccw(c129.091,89.799) 128.585,88.957 ; 128.507,66.228 ccw(c129.41,67.234) 128.585,66.163 ; 128.517,85.532 cw(c127.709,84.974) 128.584,85.42 cw(c127.709,84.974) 128.585,85.418 ; 128.517,85.532 128.585,85.532 ; 128.53,68.26 cw(c129.41,67.234) 128.585,68.305 ; 128.539,90.612 cw(c129.091,89.799) 128.585,90.641 ; 128.585,63.18 128.585,63.688 ; 128.585,63.18 129,63.18 ; 128.585,63.688 128.585,64.196 ; 128.585,63.688 129.093,63.688 ; 128.585,64.196 129.093,64.196 ; 128.585,64.196 128.585,64.704 ; 128.585,64.704 129.093,64.704 ; 128.585,64.704 128.585,65.212 ; 128.585,65.212 128.585,65.72 ; 128.585,65.212 129.093,65.212 ; 128.585,65.72 129.093,65.72 ; 128.585,65.72 128.585,66.163 ; 128.585,66.163 ccw(c129.41,67.234) 129.093,65.92 ; 128.585,68.305 cw(c129.41,67.234) 129.093,68.548 ; 128.585,68.305 128.585,68.768 ; 128.585,68.768 128.585,69.276 ; 128.585,68.768 129.093,68.768 ; 128.585,69.276 129.093,69.276 ; 128.585,69.276 128.585,69.657 ; 128.585,69.657 129.019,69.657 ; 128.585,79.503 128.585,79.944 ; 128.585,79.503 128.652,79.436 ; 128.585,79.944 128.585,80.452 ; 128.585,79.944 129.093,79.944 ; 128.585,80.452 129.093,80.452 ; 128.585,80.452 128.585,80.96 ; 128.585,80.96 129.093,80.96 ; 128.585,80.96 128.585,81.468 ; 128.585,81.468 128.712,81.468 ; 128.585,81.468 128.585,81.595 ; 128.585,81.595 128.712,81.468 ; 128.585,85.418 128.585,85.532 ; 128.585,85.532 129.093,85.532 ; 128.585,85.532 128.585,86.04 ; 128.585,86.04 128.585,86.548 ; 128.585,86.04 129.093,86.04 ; 128.585,86.548 128.585,86.675 ; 128.585,86.548 129.093,86.548 ; 128.585,86.675 128.585,87.056 ; 128.585,86.675 129.093,86.675 ; 128.585,87.056 128.585,87.373 ; 128.585,87.056 129.093,87.056 ; 128.585,87.373 128.585,87.564 ; 128.585,87.373 129.093,87.373 ; 128.585,87.564 128.585,88.072 ; 128.585,87.564 129.093,87.564 ; 128.585,88.072 128.585,88.58 ; 128.585,88.072 129.093,88.072 ; 128.585,88.58 129.093,88.58 ; 128.585,88.58 128.585,88.957 ; 128.585,88.957 ccw(c129.091,89.799) 129.091,88.816 ccw(c129.091,89.799) 129.093,88.816 ; 128.585,90.641 cw(c129.091,89.799) 129.091,90.782 cw(c129.091,89.799) 129.093,90.782 ; 128.585,90.641 128.585,91.12 ; 128.585,91.12 128.585,91.628 ; 128.585,91.12 129.093,91.12 ; 128.585,91.628 128.585,92.136 ; 128.585,91.628 129.093,91.628 ; 128.585,92.136 128.585,92.644 ; 128.585,92.136 129.093,92.136 ; 128.585,92.644 128.585,93.152 ; 128.585,92.644 129.093,92.644 ; 128.585,93.152 128.585,93.66 ; 128.585,93.152 129.093,93.152 ; 128.585,93.66 129.093,93.66 ; 128.585,93.66 128.585,94.168 ; 128.585,94.168 129.093,94.168 ; 128.585,94.168 128.585,94.676 ; 128.585,94.676 129.093,94.676 ; 128.585,94.676 128.585,95.184 ; 128.585,95.184 129.093,95.184 ; 128.585,95.184 128.585,95.692 ; 128.585,95.692 129.093,95.692 ; 128.585,95.692 128.585,95.946 ; 128.585,95.946 129.093,95.946 ; 128.608,84.577 ccw(c127.709,84.974) 128.69,85.024 129.093,85.024 ; 128.608,84.577 129.093,84.092 ; 128.652,79.436 129.093,79.436 ; 128.652,79.436 129.093,78.995 ; 128.712,81.468 130.617,79.563 ; 129,63.18 129.093,63.18 ; 129,63.18 129.093,63.087 ; 129.019,69.657 ccw(c129.983,69.848) 129.093,69.431 ; 129.093,63.087 129.093,63.18 ; 129.093,63.087 129.508,62.672 ; 129.093,63.18 129.093,63.688 ; 129.093,63.18 129.601,63.18 ; 129.093,63.688 129.093,64.196 ; 129.093,63.688 129.601,63.688 ; 129.093,64.196 129.601,64.196 ; 129.093,64.196 129.093,64.704 ; 129.093,64.704 129.601,64.704 ; 129.093,64.704 129.093,65.212 ; 129.093,65.212 129.093,65.72 ; 129.093,65.212 129.601,65.212 ; 129.093,65.72 129.601,65.72 ; 129.093,65.72 129.093,65.92 ; 129.093,65.92 ccw(c129.41,67.234) 129.41,65.882 129.601,65.882 ; 129.093,68.548 cw(c129.41,67.234) 129.41,68.586 129.601,68.586 ; 129.093,68.548 129.093,68.768 ; 129.093,68.768 129.093,69.276 ; 129.093,68.768 129.601,68.768 ; 129.093,69.276 129.093,69.431 ; 129.093,69.276 129.184,69.276 ; 129.093,69.431 ccw(c129.983,69.848) 129.184,69.276 ; 129.093,78.995 129.093,79.436 ; 129.093,78.995 129.16,78.928 ; 129.093,79.436 129.093,79.944 ; 129.093,79.436 129.601,79.436 ; 129.093,79.944 129.093,80.452 ; 129.093,79.944 129.601,79.944 ; 129.093,80.452 129.601,80.452 ; 129.093,80.452 129.093,80.96 ; 129.093,84.092 129.177,84.008 ; 129.093,84.092 129.093,84.516 ; 129.093,84.516 129.093,85.024 ; 129.093,84.516 129.601,84.516 ; 129.093,85.024 129.093,85.532 ; 129.093,85.024 129.601,85.024 ; 129.093,85.532 129.093,86.04 ; 129.093,85.532 129.601,85.532 ; 129.093,86.04 129.093,86.548 ; 129.093,86.04 129.601,86.04 ; 129.093,86.548 129.093,86.675 ; 129.093,86.548 129.601,86.548 ; 129.093,86.675 129.093,87.056 ; 129.093,86.675 129.601,86.675 ; 129.093,87.056 129.093,87.373 ; 129.093,87.056 129.601,87.056 ; 129.093,87.373 129.093,87.564 ; 129.093,87.373 129.601,87.373 ; 129.093,87.564 129.093,88.072 ; 129.093,87.564 129.601,87.564 ; 129.093,88.072 129.093,88.58 ; 129.093,88.072 129.601,88.072 ; 129.093,88.58 129.601,88.58 ; 129.093,88.58 129.093,88.816 ; 129.093,90.782 129.093,91.12 ; 129.093,91.12 129.093,91.628 ; 129.093,91.12 129.601,91.12 ; 129.093,91.628 129.093,92.136 ; 129.093,91.628 129.601,91.628 ; 129.093,92.136 129.093,92.644 ; 129.093,92.136 129.601,92.136 ; 129.093,92.644 129.093,93.152 ; 129.093,92.644 129.601,92.644 ; 129.093,93.152 129.601,93.152 ; 129.093,93.152 129.093,93.66 ; 129.093,93.66 129.601,93.66 ; 129.093,93.66 129.093,94.168 ; 129.093,94.168 129.601,94.168 ; 129.093,94.168 129.093,94.676 ; 129.093,94.676 129.601,94.676 ; 129.093,94.676 129.093,95.184 ; 129.093,95.184 129.601,95.184 ; 129.093,95.184 129.093,95.692 ; 129.093,95.692 129.601,95.692 ; 129.093,95.692 129.093,95.946 ; 129.093,95.946 129.601,95.946 ; 129.16,78.928 129.601,78.928 ; 129.16,78.928 129.317,78.771 ; 129.177,84.008 129.601,83.584 ; 129.177,84.008 129.601,84.008 ; 129.184,69.276 ccw(c129.983,69.848) 129.601,68.943 ; 129.317,78.771 cw(c128.712,78.166) 129.494,78.514 ccw(c128.712,78.166) 129.317,78.771 ; 129.508,62.672 129.601,62.672 ; 129.508,62.672 129.601,62.579 ; 129.543,78.42 cw(c128.763,78.069) 129.601,78.242 ; 129.543,78.42 cw(c128.763,78.069) 129.601,78.242 ; 129.543,78.42 ccw(c128.763,78.069) 129.496,78.51 cw(c128.763,78.069) 129.543,78.42 ; 129.543,78.42 129.601,78.42 ; 129.601,62.579 129.601,62.672 ; 129.601,62.579 130.016,62.164 130.109,62.164 ; 129.601,62.672 130.109,62.672 ; 129.601,62.672 129.601,63.18 ; 129.601,63.18 130.109,63.18 ; 129.601,63.18 129.601,63.688 ; 129.601,63.688 129.601,64.196 ; 129.601,63.688 130.109,63.688 ; 129.601,64.196 130.109,64.196 ; 129.601,64.196 129.601,64.704 ; 129.601,64.704 130.109,64.704 ; 129.601,64.704 129.601,65.212 ; 129.601,65.212 129.601,65.72 ; 129.601,65.212 130.109,65.212 ; 129.601,65.72 129.601,65.882 ; 129.601,65.72 130.109,65.72 ; 129.601,65.882 130.109,65.882 ; 129.601,68.586 129.601,68.768 ; 129.601,68.586 130.109,68.586 ; 129.601,68.768 130.109,68.768 ; 129.601,68.768 129.601,68.943 ; 129.601,68.943 ccw(c129.983,69.848) 130.102,68.873 ccw(c129.983,69.848) 130.109,68.874 ; 129.601,78.242 cw(c128.763,78.069) 129.619,78.069 ; 129.601,78.242 cw(c128.763,78.069) 129.619,78.069 ; 129.601,78.242 129.601,78.42 ; 129.601,78.42 129.601,78.928 ; 129.601,78.42 130.109,78.42 ; 129.601,78.928 129.601,79.436 ; 129.601,78.928 130.109,78.928 ; 129.601,79.436 129.601,79.944 ; 129.601,79.436 130.109,79.436 ; 129.601,79.944 129.601,80.452 ; 129.601,79.944 130.109,79.944 ; 129.601,83.584 129.685,83.5 ; 129.601,83.584 129.601,84.008 ; 129.601,84.008 129.601,84.516 ; 129.601,84.008 130.109,84.008 ; 129.601,84.516 130.109,84.516 ; 129.601,84.516 129.601,85.024 ; 129.601,85.024 129.601,85.532 ; 129.601,85.024 130.109,85.024 ; 129.601,85.532 129.601,86.04 ; 129.601,85.532 130.109,85.532 ; 129.601,86.04 129.601,86.548 ; 129.601,86.04 130.109,86.04 ; 129.601,86.548 129.601,86.675 ; 129.601,86.548 130.109,86.548 ; 129.601,86.675 129.601,87.056 ; 129.601,86.675 130.109,86.675 ; 129.601,87.056 129.601,87.373 ; 129.601,87.056 130.109,87.056 ; 129.601,87.373 129.601,87.564 ; 129.601,87.373 130.109,87.373 ; 129.601,87.564 129.601,88.072 ; 129.601,87.564 130.109,87.564 ; 129.601,88.072 129.601,88.58 ; 129.601,88.072 130.109,88.072 ; 129.601,88.58 129.601,88.943 ; 129.601,88.58 130.109,88.58 ; 129.601,88.943 130.109,88.943 ; 129.601,90.655 130.109,90.655 ; 129.601,90.655 129.601,91.12 ; 129.601,91.12 129.601,91.628 ; 129.601,91.12 130.109,91.12 ; 129.601,91.628 129.601,92.136 ; 129.601,91.628 130.109,91.628 ; 129.601,92.136 129.601,92.644 ; 129.601,92.136 130.109,92.136 ; 129.601,92.644 129.601,93.152 ; 129.601,92.644 130.109,92.644 ; 129.601,93.152 129.601,93.66 ; 129.601,93.152 130.109,93.152 ; 129.601,93.66 130.109,93.66 ; 129.601,93.66 129.601,94.168 ; 129.601,94.168 130.109,94.168 ; 129.601,94.168 129.601,94.676 ; 129.601,94.676 130.109,94.676 ; 129.601,94.676 129.601,95.184 ; 129.601,95.184 130.109,95.184 ; 129.601,95.184 129.601,95.692 ; 129.601,95.692 pad.@130.109,95.692 ; 129.601,95.692 129.601,95.946 ; 129.601,95.946 130.109,95.946 ; 129.619,72.832 130.109,72.832 ; 129.619,72.832 129.619,73.34 ; 129.619,72.832 129.619,72.5 129.795,72.324 ; 129.619,73.34 130.109,73.34 ; 129.619,73.34 129.619,73.848 ; 129.619,73.848 130.109,73.848 ; 129.619,73.848 129.619,74.356 ; 129.619,74.356 130.109,74.356 ; 129.619,74.356 129.619,74.864 ; 129.619,74.864 130.109,74.864 ; 129.619,74.864 129.619,75.372 ; 129.619,75.372 130.109,75.372 ; 129.619,75.372 129.619,75.88 ; 129.619,75.88 130.109,75.88 ; 129.619,75.88 129.619,76.388 ; 129.619,76.388 130.109,76.388 ; 129.619,76.388 129.619,76.896 ; 129.619,76.896 130.109,76.896 ; 129.619,76.896 129.619,77.404 ; 129.619,77.404 129.619,77.912 ; 129.619,77.404 130.109,77.404 ; 129.619,77.912 130.109,77.912 ; 129.619,77.912 129.619,78.069 ; 129.685,83.5 130.109,83.076 ; 129.685,83.5 130.109,83.5 ; 129.795,72.324 130.109,72.324 ; 129.795,72.324 130.303,71.816 ; 130.109,62.164 130.617,62.164 ; 130.109,62.164 130.109,62.672 ; 130.109,62.672 130.617,62.672 ; 130.109,62.672 130.109,63.18 ; 130.109,63.18 130.617,63.18 ; 130.109,63.18 130.109,63.688 ; 130.109,63.688 130.109,64.196 ; 130.109,63.688 130.617,63.688 ; 130.109,64.196 130.617,64.196 ; 130.109,64.196 130.109,64.704 ; 130.109,64.704 130.617,64.704 ; 130.109,64.704 130.109,65.212 ; 130.109,65.212 130.109,65.72 ; 130.109,65.212 130.617,65.212 ; 130.109,65.72 130.109,65.882 ; 130.109,65.72 130.617,65.72 ; 130.109,65.882 130.617,65.882 ; 130.109,68.586 130.617,68.586 ; 130.109,68.586 130.109,68.768 ; 130.109,68.768 130.617,68.768 ; 130.109,68.768 130.109,68.874 ; 130.109,68.874 ccw(c129.983,69.848) 130.617,69.098 ; 130.109,72.324 130.109,72.832 ; 130.109,72.324 130.617,72.324 ; 130.109,72.832 130.109,73.34 ; 130.109,72.832 130.617,72.832 ; 130.109,73.34 130.109,73.848 ; 130.109,73.34 130.617,73.34 ; 130.109,73.848 130.109,74.356 ; 130.109,73.848 130.617,73.848 ; 130.109,74.356 130.109,74.864 ; 130.109,74.356 130.617,74.356 ; 130.109,74.864 130.109,75.372 ; 130.109,74.864 130.617,74.864 ; 130.109,75.372 130.109,75.88 ; 130.109,75.372 130.617,75.372 ; 130.109,75.88 130.109,76.388 ; 130.109,75.88 130.617,75.88 ; 130.109,76.388 130.109,76.896 ; 130.109,76.388 130.617,76.388 ; 130.109,76.896 130.109,77.404 ; 130.109,76.896 130.617,76.896 ; 130.109,77.404 130.109,77.912 ; 130.109,77.404 130.617,77.404 ; 130.109,77.912 130.617,77.912 ; 130.109,77.912 130.109,78.42 ; 130.109,78.42 130.617,78.42 ; 130.109,78.42 130.109,78.928 ; 130.109,78.928 130.617,78.928 ; 130.109,78.928 130.109,79.436 ; 130.109,79.436 130.617,79.436 ; 130.109,79.436 130.109,79.944 ; 130.109,83.076 130.193,82.992 ; 130.109,83.076 130.109,83.5 ; 130.109,83.5 130.109,84.008 ; 130.109,83.5 130.617,83.5 ; 130.109,84.008 130.109,84.516 ; 130.109,84.008 130.617,84.008 ; 130.109,84.516 130.109,85.024 ; 130.109,84.516 130.617,84.516 ; 130.109,85.024 130.109,85.532 ; 130.109,85.024 130.617,85.024 ; 130.109,85.532 130.109,86.04 ; 130.109,85.532 130.617,85.532 ; 130.109,86.04 130.109,86.548 ; 130.109,86.04 130.617,86.04 ; 130.109,86.548 130.109,86.675 ; 130.109,86.548 130.617,86.548 ; 130.109,86.675 130.109,87.056 ; 130.109,86.675 130.617,86.675 ; 130.109,87.056 130.617,87.056 ; 130.109,87.056 130.109,87.373 ; 130.109,87.373 130.109,87.564 ; 130.109,87.373 130.617,87.373 ; 130.109,87.564 130.109,88.072 ; 130.109,87.564 130.617,87.564 ; 130.109,88.072 130.109,88.58 ; 130.109,88.072 130.617,88.072 ; 130.109,88.58 130.109,88.943 ; 130.109,88.58 130.617,88.58 ; 130.109,88.943 130.617,88.943 ; 130.109,90.655 130.109,91.12 ; 130.109,90.655 130.617,90.655 ; 130.109,91.12 130.109,91.628 ; 130.109,91.12 130.617,91.12 ; 130.109,91.628 130.109,92.136 ; 130.109,91.628 130.617,91.628 ; 130.109,92.136 130.109,92.644 ; 130.109,92.136 130.617,92.136 ; 130.109,92.644 130.109,93.152 ; 130.109,92.644 130.617,92.644 ; 130.109,93.152 130.109,93.66 ; 130.109,93.152 130.617,93.152 ; 130.109,93.66 130.109,94.168 ; 130.109,93.66 130.617,93.66 ; 130.109,94.168 130.109,94.676 ; 130.109,94.168 130.617,94.168 ; 130.109,94.676 130.109,95.184 ; 130.109,94.676 130.617,94.676 ; 130.109,95.184 130.617,95.184 ; 130.109,95.184 pad.@130.109,95.692 ; pad.@130.109,95.692 130.109,95.946 ; pad.@130.109,95.692 pad.@130.617,95.692 ; 130.109,95.946 130.617,95.946 ; 130.193,82.992 130.617,82.568 ; 130.193,82.992 130.617,82.992 ; 130.303,71.816 130.617,71.816 ; 130.303,71.816 130.539,71.58 ; 130.539,71.58 cw(c129.934,70.975) 130.617,71.49 ; 130.539,71.58 cw(c129.934,70.975) 130.617,71.49 ; 130.617,62.164 130.617,62.672 ; 130.617,62.164 131.125,62.164 ; 130.617,62.672 130.617,63.18 ; 130.617,62.672 131.125,62.672 ; 130.617,63.18 130.617,63.688 ; 130.617,63.18 131.125,63.18 ; 130.617,63.688 130.617,64.196 ; 130.617,63.688 131.125,63.688 ; 130.617,64.196 130.617,64.704 ; 130.617,64.196 131.125,64.196 ; 130.617,64.704 130.617,65.212 ; 130.617,64.704 131.125,64.704 ; 130.617,65.212 130.617,65.72 ; 130.617,65.212 131.125,65.212 ; 130.617,65.72 130.617,65.882 ; 130.617,65.72 131.125,65.72 ; 130.617,65.882 131.125,65.882 ; 130.617,68.586 130.617,68.768 ; 130.617,68.586 131.125,68.586 ; 130.617,68.768 131.125,68.768 ; 130.617,68.768 130.617,69.098 ; 130.617,69.098 ccw(c129.983,69.848) 130.708,69.185 ; 130.617,71.49 cw(c129.934,70.975) 130.722,71.308 ; 130.617,71.49 cw(c129.934,70.975) 130.722,71.308 ; 130.617,71.49 130.617,71.816 ; 130.617,71.816 130.617,72.324 ; 130.617,71.816 131.125,71.816 ; 130.617,72.324 130.617,72.832 ; 130.617,72.324 131.125,72.324 ; 130.617,72.832 130.617,73.34 ; 130.617,72.832 131.125,72.832 ; 130.617,73.34 130.617,73.848 ; 130.617,73.34 131.125,73.34 ; 130.617,73.848 130.617,74.356 ; 130.617,73.848 131.125,73.848 ; 130.617,74.356 130.617,74.864 ; 130.617,74.356 131.125,74.356 ; 130.617,74.864 130.617,75.372 ; 130.617,74.864 131.125,74.864 ; 130.617,75.372 130.617,75.88 ; 130.617,75.372 131.125,75.372 ; 130.617,75.88 130.617,76.388 ; 130.617,75.88 131.125,75.88 ; 130.617,76.388 130.617,76.896 ; 130.617,76.388 131.125,76.388 ; 130.617,76.896 130.617,77.404 ; 130.617,76.896 131.125,76.896 ; 130.617,77.404 130.617,77.912 ; 130.617,77.404 131.125,77.404 ; 130.617,77.912 130.617,78.42 ; 130.617,77.912 131.125,77.912 ; 130.617,78.42 130.617,78.928 ; 130.617,78.42 131.125,78.42 ; 130.617,78.928 130.617,79.436 ; 130.617,78.928 131.125,78.928 ; 130.617,79.436 130.617,79.563 ; 130.617,79.436 130.744,79.436 ; 130.617,79.563 130.744,79.436 ; 130.617,82.568 130.701,82.484 ; 130.617,82.568 130.617,82.992 ; 130.617,82.992 131.125,82.992 ; 130.617,82.992 130.617,83.5 ; 130.617,83.5 130.617,84.008 ; 130.617,83.5 131.125,83.5 ; 130.617,84.008 130.617,84.516 ; 130.617,84.008 131.125,84.008 ; 130.617,84.516 131.125,84.516 ; 130.617,84.516 130.617,85.024 ; 130.617,85.024 130.617,85.532 ; 130.617,85.024 131.125,85.024 ; 130.617,85.532 130.617,86.04 ; 130.617,85.532 131.125,85.532 ; 130.617,86.04 130.617,86.548 ; 130.617,86.04 131.125,86.04 ; 130.617,86.548 130.617,86.675 ; 130.617,86.548 131.125,86.548 ; 130.617,86.675 130.617,87.056 ; 130.617,86.675 130.98,86.675 130.98,87.056 ; 130.617,87.056 130.617,87.373 ; 130.617,87.056 130.98,87.056 ; 130.617,87.373 130.98,87.373 ; 130.617,87.373 130.617,87.564 ; 130.617,87.564 130.617,88.072 ; 130.617,87.564 130.98,87.564 ; 130.617,88.072 130.617,88.58 ; 130.617,88.072 130.98,88.072 ; 130.617,88.58 130.617,88.943 ; 130.617,88.58 130.98,88.58 ; 130.617,88.943 130.98,88.943 130.98,88.58 ; 130.617,90.655 130.617,91.12 ; 130.617,90.655 131.125,90.655 ; 130.617,91.12 130.617,91.628 ; 130.617,91.12 131.125,91.12 ; 130.617,91.628 130.617,92.136 ; 130.617,91.628 131.125,91.628 ; 130.617,92.136 130.617,92.644 ; 130.617,92.136 131.125,92.136 ; 130.617,92.644 130.617,93.152 ; 130.617,92.644 131.125,92.644 ; 130.617,93.152 130.617,93.66 ; 130.617,93.152 131.125,93.152 ; 130.617,93.66 130.617,94.168 ; 130.617,93.66 131.125,93.66 ; 130.617,94.168 130.617,94.676 ; 130.617,94.168 131.125,94.168 ; 130.617,94.676 130.617,95.184 ; 130.617,94.676 131.125,94.676 ; 130.617,95.184 131.125,95.184 ; 130.617,95.184 pad.@130.617,95.692 ; pad.@130.617,95.692 130.617,95.946 ; pad.@130.617,95.692 131.125,95.692 ; 130.617,95.946 131.125,95.946 ; 130.701,82.484 131.125,82.06 ; 130.701,82.484 131.125,82.484 ; 130.708,69.185 ccw(c129.983,69.848) 130.781,69.276 ; 130.708,69.185 131.125,68.768 ; 130.722,71.308 cw(c129.934,70.975) 130.79,70.975 ; 130.722,71.308 cw(c129.934,70.975) 130.79,70.975 ; 130.722,71.308 131.125,71.308 ; 130.744,79.436 131.125,79.055 ; 130.781,69.276 ccw(c129.983,69.848) 130.946,69.657 ; 130.781,69.276 131.125,69.276 ; 130.79,70.409 cw(c129.983,69.848) 130.859,70.292 ; 130.79,70.409 130.79,70.8 ; 130.79,70.8 131.125,70.8 ; 130.79,70.8 130.79,70.975 ; 130.859,70.292 cw(c129.983,69.848) 130.965,69.848 cw(c129.983,69.848) 130.963,69.784 ; 130.859,70.292 131.125,70.292 ; 130.946,69.657 ccw(c129.983,69.848) 130.963,69.784 ; 130.946,69.657 131.125,69.657 ; 130.963,69.784 131.125,69.784 ; 130.98,87.056 131.125,87.056 ; 130.98,87.056 130.98,87.373 ; 130.98,87.373 131.062,87.373 131.125,87.31 ; 130.98,87.373 130.98,87.564 ; 130.98,87.564 130.98,88.072 ; 130.98,88.072 130.98,88.58 ; 131.125,62.164 131.125,62.672 ; 131.125,62.164 131.633,62.164 ; 131.125,62.672 131.125,63.18 ; 131.125,62.672 131.633,62.672 ; 131.125,63.18 131.125,63.688 ; 131.125,63.18 131.633,63.18 ; 131.125,63.688 131.125,64.196 ; 131.125,63.688 131.633,63.688 ; 131.125,64.196 131.125,64.704 ; 131.125,64.196 131.633,64.196 ; 131.125,64.704 131.125,65.212 ; 131.125,64.704 131.633,64.704 ; 131.125,65.212 131.125,65.72 ; 131.125,65.212 131.633,65.212 ; 131.125,65.72 131.125,65.882 ; 131.125,65.72 131.633,65.72 ; 131.125,65.882 131.633,65.882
